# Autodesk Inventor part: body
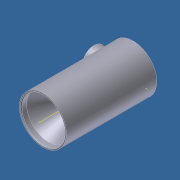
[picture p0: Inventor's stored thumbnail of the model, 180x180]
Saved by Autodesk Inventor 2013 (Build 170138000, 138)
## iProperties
Created: 2000-03
Part Number: body
Project: 9907-000-182
Document SubType Name: Modeling
Designer: Peter Roberts
Density: 2.71 g/cm^3
Material: Aluminum
Mass: 386.996 g
Surface Area: 286.9 cm^2
Volume: 142.803 cm^3
Manager: Dave Ford
Company: Autodesk Inc.
Control State: 0
Checked Out: False
Master: False
Shininess: 0.0
Length Units: 11269
Angle Units: 11279
Time Units: 11290
Mass Units: 11284
Length Display Precision: 1
Angle Display Precision: 1
Compacted: True
PropertySet Name: Model Information
Density: 0.0
Volumn: 0.0
Area: 0.0
Title: Valve Body
Subject: Tutorial #3 - part file
Author: Peter Roberts
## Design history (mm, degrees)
node "y-z Plane"
  node "x-z Plane"
  node "x-y Plane"
node "Extrusion1" dims "d0" = 100, "d1" = 0
  sketch "Sketch1"
    geometry: C1 r 26 at (0, 0)
    constraints: 1 centre point
    dimensions: "d16" = 52 diameter of C1
workplane "Work Plane1"
node "Extrusion2" dims "d3" = 76.2, "d4" = 0
  sketch "Sketch3"
    geometry: L1 (-25.4, 0)-(25.4, 0) reference; L2 (26, 0)-(26, 100) reference; C1 r 12.5 at (0, 12.5)
    constraints: 1 centre point
    dimensions: "d10" = 25 diameter of C1; "d11" = 12.5 distance from line of C1.centre L1; "d18" = 26 distance from line of L2 C1.centre
node "Revolution1" dims "d5" = 90 deg
  sketch "Sketch4"
    geometry: L1 (-24, 100)-(-24, 94); L2 (-24, 94)-(-12, 73); L3 (-12, 73)-(-12, 0); L4 (0, 66.675)-(0, 44.45); L5 (-24, 100)-(0, 100); L6 (0, 100)-(0, 0) reference; L7 (0, 0)-(-12, 0); L8 (-25.4, 88.9)-(25.4, 88.9) reference
    constraints: 14 end point, 2 parallel, 2 vertical, 1 collinear, 1 perpendicular
    dimensions: "d12" = 24 distance between parallel lines of L1 L6; "d13" = 6 distance from line of L1.end L5; "d14" = 27 distance from line of L2.end L5; "d15" = 12 distance between parallel lines of L3 L6
node "Extrusion3" dims "d6" = 41.75, "d7" = 0
  sketch "Sketch5"
    geometry: C1 r 12.5 at (0, 0) reference; C2 r 10 at (0, 0)
    constraints: 1 centre point, 1 concentric
    dimensions: "d17" = 20 diameter of C2
node "Chamfer1" dims "d8" = 0.8, "d9" = 0.8, "d19" = 45 deg
workaxis "Work Axis2"
workaxis "Work Axis3"
body "Solid1"
other parameters: "d2" = -31.75
